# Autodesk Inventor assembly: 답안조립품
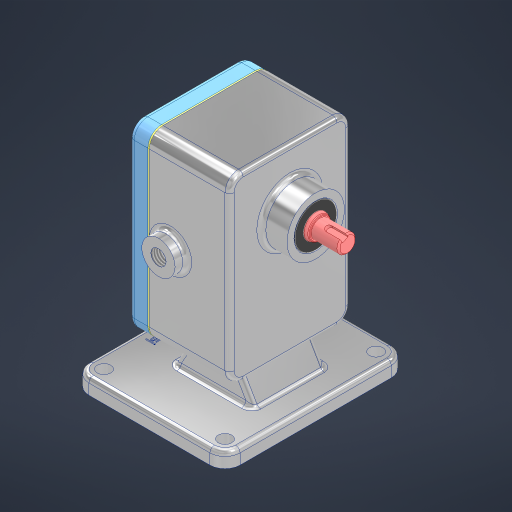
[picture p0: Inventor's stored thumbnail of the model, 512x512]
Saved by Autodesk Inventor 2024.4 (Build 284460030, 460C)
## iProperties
Created: 2026-10
Part Number: 답안조립품
Document SubType Name: Assembly
Designer: user
Author: user
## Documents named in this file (10)
- C:\Users\user\Desktop\761003V1005\답안조립품.iam
- C:\Users\user\Desktop\761003V1005\본체.ipt
- C:\Users\user\Desktop\761003V1005\커버\커버\커버.ipt
- C:\Users\user\Desktop\761003V1005\베어링 부시\베어링 부시\베어링 부시.ipt
- C:\Users\user\Desktop\761003V1005\오일 실 16 28 7\오일 실 16 28 7\오일 실 16 28 7.ipt
- C:\Users\user\Desktop\761003V1005\구동 축\구동 축\구동 축.ipt
- C:\Users\user\Desktop\761003V1005\종동 축\종동 축\종동 축.ipt
- C:\Users\user\Desktop\761003V1005\평행 키 6x6x18\평행 키 6x6x18\평행 키 6x6x18.ipt
- C:\Users\user\Desktop\761003V1005\개스킷\개스킷\개스킷.ipt
- C:\Users\user\Desktop\761003V1005\스퍼 기어\스퍼 기어\스퍼 기어.ipt
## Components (2 placed, 2 different names)
1. 구동 축:1
2. 개스킷:1 — 플러쉬:2
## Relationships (1: Flush 1)
- 플러쉬:2 [Flush]: 개스킷:1
